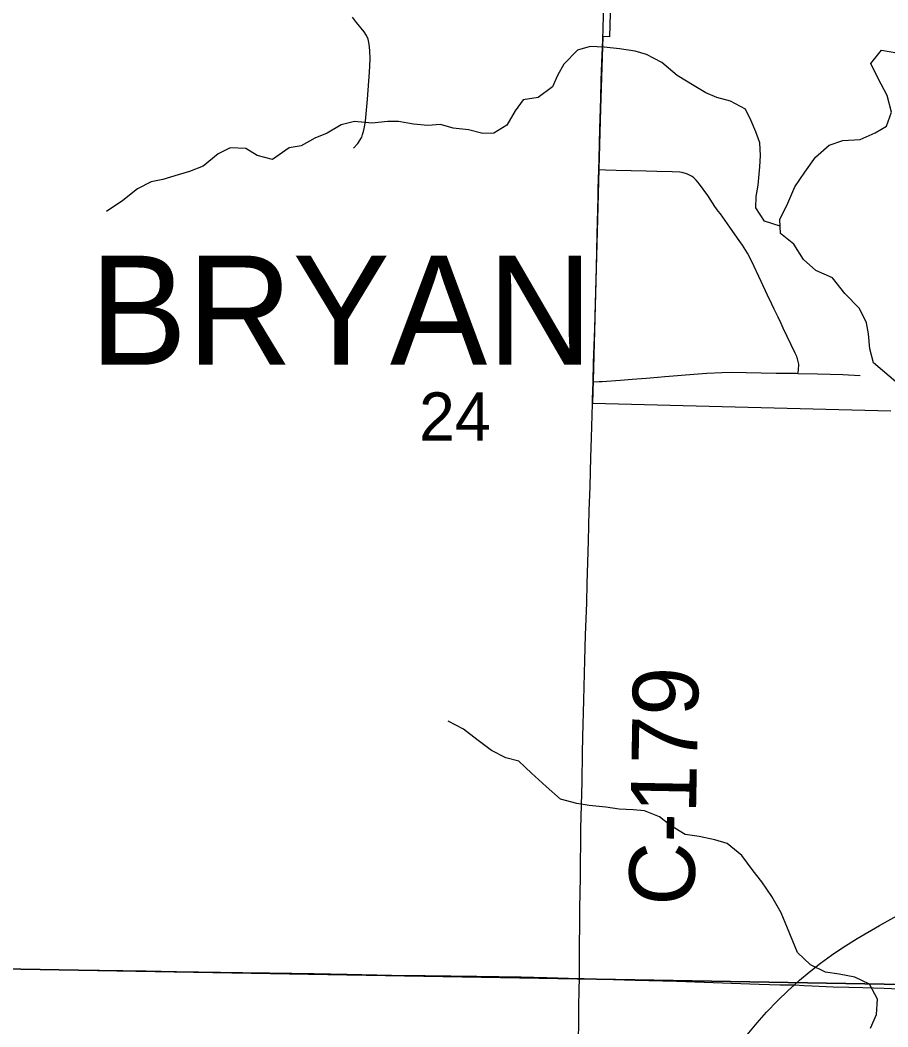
# Model space of a CAD drawing. Extents: x 0 to 34, y 0 to 22.
# Drawn here: x 5.686 to 6.439, y 18.41 to 19.283 of the extents above; entities that cross this region are included whole.
import ezdxf

# ---------------------------------------------------------------- set-up
doc = ezdxf.new("R2010")
doc.units = 0
for name, color, linetype in [('GM_X_City_Street', 7, 'Continuous'), ('GM_X_Corporation_Text', 7, 'Continuous'), ('GM_X_County_Road', 7, 'Continuous'), ('GM_X_County_Road_Text', 7, 'Continuous'), ('GM_X_Minor_River', 7, 'Continuous'), ('GM_X_Section', 7, 'Continuous'), ('GM_X_Section_Text', 7, 'Continuous'), ('GM_X_Township_Road', 7, 'Continuous'), ('GM_X_US_Route', 7, 'Continuous')]:
    doc.layers.add(name, color=color, linetype=linetype)

msp = doc.modelspace()

# ---------------------------------------------------------------- linework, layer by layer
at = {"layer": 'GM_X_City_Street'}
for points in [[(6.361, 18.97709), (6.3613, 18.97949), (6.36155, 18.98158), (6.36168, 18.98336), (6.36169, 18.9852), (6.36125, 18.98749), (6.36094, 18.98856), (6.3606, 18.9896), (6.36024, 18.99065), (6.35985, 18.99172), (6.35867, 18.99451), (6.34827, 19.01629), (6.34643, 19.0202), (6.34374, 19.02578), (6.34037, 19.03289), (6.33838, 19.03719), (6.33458, 19.04497), (6.32913, 19.05679), (6.32062, 19.07476), (6.31707, 19.08131), (6.31282, 19.08815), (6.30862, 19.09429), (6.30187, 19.10386), (6.29368, 19.11545), (6.29181, 19.11789), (6.2904, 19.11992), (6.28899, 19.12196), (6.28274, 19.13122), (6.27555, 19.14133), (6.27281, 19.14467), (6.27053, 19.14677), (6.26911, 19.14779), (6.26796, 19.1485), (6.26516, 19.14983), (6.2634, 19.15045), (6.26221, 19.1508), (6.26049, 19.15121), (6.25857, 19.15153), (6.25175, 19.15197), (6.23871, 19.15226), (6.22941, 19.15253), (6.20336, 19.15318), (6.19406, 19.15345), (6.18827, 19.15362)], [(6.1833, 18.96964), (6.18869, 18.96991), (6.19116, 18.97003), (6.20717, 18.97131), (6.21705, 18.97209), (6.22944, 18.97305), (6.23933, 18.97384), (6.24551, 18.97432), (6.24922, 18.97462), (6.27081, 18.97643), (6.28194, 18.9773), (6.29496, 18.97792), (6.30302, 18.97808), (6.34215, 18.97737), (6.35953, 18.97711), (6.361, 18.97709), (6.37791, 18.97665), (6.39987, 18.97598), (6.41477, 18.97533)]]:
    msp.add_lwpolyline(points, dxfattribs=at)
at = {"layer": 'GM_X_County_Road'}
for points in [[(6.18827, 19.15362), (6.18854, 19.1632), (6.1892, 19.18905), (6.18997, 19.21591), (6.19043, 19.23106), (6.19097, 19.24659), (6.19164, 19.26648), (6.19262, 19.29755), (6.19346, 19.32426), (6.19378, 19.33703)], [(6.1833, 18.96964), (6.18378, 18.98621), (6.18481, 19.01603), (6.18549, 19.03779), (6.18616, 19.06889), (6.18689, 19.09744), (6.1877, 19.12981), (6.18782, 19.13729), (6.18827, 19.15362)], [(6.18281, 18.95063), (6.18286, 18.95452), (6.1833, 18.96964)], [(6.17143, 18.45214), (6.17154, 18.45962), (6.17152, 18.47292), (6.17155, 18.4835), (6.17174, 18.49654), (6.17195, 18.51279), (6.17226, 18.54011), (6.17274, 18.58232), (6.17369, 18.62271), (6.17408, 18.64756), (6.17441, 18.66185), (6.17521, 18.69354), (6.17622, 18.72833), (6.17685, 18.75007), (6.17779, 18.77804), (6.17814, 18.79482), (6.17929, 18.83146), (6.17992, 18.85818), (6.18066, 18.87867), (6.181, 18.89173), (6.18138, 18.90403), (6.18193, 18.92127), (6.18281, 18.95063)], [(6.35793, 18.44665), (6.36223, 18.45067), (6.37078, 18.45782), (6.3805, 18.46552), (6.39004, 18.47243), (6.39983, 18.47899), (6.41244, 18.48689), (6.43175, 18.49816), (6.46106, 18.51451), (6.54114, 18.55854), (6.58302, 18.58174), (6.63577, 18.61095), (6.65918, 18.62387), (6.67924, 18.63516), (6.68917, 18.64087)], [(5.62837, 18.46124), (5.63114, 18.46121), (5.69518, 18.46029), (5.73517, 18.45966), (5.79587, 18.45876), (5.82198, 18.4584), (5.87918, 18.45731), (5.9028, 18.45697), (5.94133, 18.45645), (5.96991, 18.45581), (6.00846, 18.45514), (6.03767, 18.45474), (6.08241, 18.45408), (6.12093, 18.45349), (6.14329, 18.453), (6.17143, 18.45214)], [(6.16955, 18.19819), (6.16945, 18.21008), (6.16944, 18.2281), (6.16954, 18.24302), (6.16971, 18.26291), (6.16973, 18.27348), (6.16996, 18.29211), (6.16997, 18.30021), (6.17007, 18.3136), (6.17024, 18.33498), (6.17028, 18.35363), (6.17044, 18.37103), (6.17062, 18.40088), (6.1708, 18.41204), (6.17106, 18.42758), (6.17133, 18.44262), (6.17143, 18.45214)], [(6.17143, 18.45214), (6.17559, 18.45209), (6.20106, 18.45127), (6.21972, 18.45078), (6.25576, 18.44973), (6.32721, 18.44723), (6.34539, 18.44663), (6.35237, 18.44655), (6.35793, 18.44665)], [(6.16955, 18.19819), (6.17108, 18.19969), (6.18824, 18.21684), (6.19944, 18.22854), (6.20894, 18.23927), (6.21684, 18.24893), (6.22435, 18.25888), (6.23114, 18.26858), (6.24032, 18.28267), (6.25243, 18.30225), (6.28477, 18.35608), (6.29552, 18.37352), (6.30207, 18.38332), (6.30931, 18.39338), (6.31686, 18.40323), (6.32557, 18.41373), (6.33379, 18.423), (6.34323, 18.43286), (6.35258, 18.44191), (6.35793, 18.44665)], [(6.35793, 18.44665), (6.36634, 18.44606), (6.37341, 18.44573), (6.39156, 18.44504), (6.40513, 18.44458), (6.41716, 18.44425), (6.43567, 18.44368), (6.45502, 18.44294), (6.49085, 18.44171), (6.51197, 18.44119), (6.53308, 18.44062), (6.55419, 18.44002), (6.58898, 18.43913), (6.60762, 18.43887), (6.63185, 18.43866), (6.65298, 18.4386), (6.67388, 18.43883), (6.68534, 18.43905), (6.68712, 18.43912), (6.68875, 18.43925)]]:
    msp.add_lwpolyline(points, dxfattribs=at)
at = {"layer": 'GM_X_Minor_River'}
for points in [[(6.34547, 19.10465), (6.3319, 19.10904), (6.32454, 19.12057), (6.32473, 19.13043), (6.32644, 19.14026), (6.32788, 19.15618), (6.32845, 19.16603), (6.32791, 19.17705), (6.3243, 19.1866), (6.32031, 19.19617), (6.31558, 19.20613), (6.30244, 19.21321), (6.29075, 19.21648), (6.28097, 19.22046), (6.27084, 19.22635), (6.25622, 19.23536), (6.24279, 19.24663), (6.22966, 19.25371), (6.21985, 19.25656), (6.20624, 19.25872), (6.193, 19.26012), (6.18087, 19.26073), (6.16982, 19.25753), (6.15782, 19.24524), (6.15233, 19.23548), (6.14797, 19.22569), (6.13565, 19.21644), (6.12272, 19.21442), (6.11571, 19.20469), (6.10864, 19.1923), (6.09713, 19.18531), (6.08765, 19.18511), (6.0752, 19.18839), (6.06195, 19.18978), (6.05102, 19.19303), (6.04, 19.19211), (6.02751, 19.19311), (6.01466, 19.19563), (6.00518, 19.19544), (5.99151, 19.19418), (5.97637, 19.19562), (5.96493, 19.1928), (5.95266, 19.18545), (5.94196, 19.1811), (5.93007, 19.1745), (5.9198, 19.1728), (5.90519, 19.16245), (5.89199, 19.16613), (5.88225, 19.17201), (5.86861, 19.17265), (5.85827, 19.16754), (5.84517, 19.15678), (5.83332, 19.15208), (5.82341, 19.14923), (5.81006, 19.14532), (5.80016, 19.14323), (5.78829, 19.13701), (5.77558, 19.12701), (5.76137, 19.11742)], [(6.44787, 18.9679), (6.42661, 18.98615), (6.42343, 18.99835), (6.42216, 19.01128), (6.42045, 19.0208), (6.41425, 19.03344), (6.4016, 19.04621), (6.39087, 19.06008), (6.37659, 19.06643), (6.36577, 19.07575), (6.35731, 19.08919), (6.34573, 19.09852), (6.34521, 19.11068), (6.3523, 19.12458), (6.35827, 19.13889), (6.36685, 19.15163), (6.37621, 19.16473), (6.38816, 19.17512), (6.39999, 19.17907), (6.4148, 19.17992), (6.4278, 19.18574), (6.43778, 19.19162), (6.44218, 19.20367), (6.43829, 19.21817), (6.43061, 19.23274), (6.42403, 19.24577), (6.43336, 19.25736), (6.44659, 19.2552)], [(6.42381, 18.40904), (6.42897, 18.42109), (6.42999, 18.43434), (6.42304, 18.44738), (6.41026, 18.45332), (6.39665, 18.45586), (6.38493, 18.4576), (6.37178, 18.46393), (6.36062, 18.47477), (6.35664, 18.48471), (6.35192, 18.49581), (6.34649, 18.50919), (6.33843, 18.52339), (6.32957, 18.53608), (6.32217, 18.54571), (6.31219, 18.5588), (6.29949, 18.56929), (6.28894, 18.57253), (6.27534, 18.57545), (6.26324, 18.5772), (6.2505, 18.58504), (6.24079, 18.59244), (6.22799, 18.59762), (6.21815, 18.59856), (6.20603, 18.59918), (6.19431, 18.60092), (6.17993, 18.60234), (6.16934, 18.60406), (6.155, 18.60776), (6.1427, 18.61862), (6.13003, 18.63025), (6.11886, 18.64071), (6.10754, 18.64358), (6.09514, 18.64989), (6.08244, 18.65963), (6.07086, 18.66858), (6.05771, 18.67528)]]:
    msp.add_lwpolyline(points, dxfattribs=at)
at = {"layer": 'GM_X_Section'}
for points in [[(5.68333, 19.46665), (6.6975, 19.43966), (6.68531, 18.44295), (5.65349, 18.46087)], [(5.65349, 18.46087), (6.68531, 18.44295), (6.66543, 17.44151), (5.65514, 17.45551)]]:
    msp.add_lwpolyline(points, close=True, dxfattribs=at)
at = {"layer": 'GM_X_Township_Road'}
msp.add_lwpolyline([(5.97556, 19.17247), (5.97933, 19.17659), (5.98145, 19.17965), (5.98265, 19.18202), (5.98342, 19.18419), (5.98433, 19.1869), (5.98488, 19.18957), (5.98539, 19.19232), (5.98584, 19.1957), (5.98759, 19.21488), (5.98934, 19.23843), (5.98991, 19.2496), (5.9898, 19.25705), (5.98926, 19.26261), (5.98827, 19.26684), (5.98683, 19.27027), (5.98488, 19.27343), (5.97807, 19.2815), (5.97479, 19.28602)], dxfattribs=at)
at = {"layer": 'GM_X_US_Route'}
msp.add_lwpolyline([(6.19959, 19.33967), (6.19741, 19.26906), (6.19172, 19.26921), (6.18961, 19.20677), (6.1882, 19.15434), (6.18325, 18.97081), (6.18274, 18.95135), (6.44148, 18.94463)], dxfattribs=at)

# ---------------------------------------------------------------- texts
at = {"layer": 'GM_X_Corporation_Text'}
msp.add_text('BRYAN', height=0.094697, rotation=0.00001, dxfattribs=at).set_placement((5.74673, 18.9845))
at = {"layer": 'GM_X_County_Road_Text'}
msp.add_text('C-179', height=0.056818, rotation=88.90961, dxfattribs=at).set_placement((6.27102, 18.51496))
at = {"layer": 'GM_X_Section_Text'}
msp.add_text('24', height=0.041856, rotation=0.00001, dxfattribs=at).set_placement((6.03232, 18.91872))

doc.saveas('drawing.dxf')
